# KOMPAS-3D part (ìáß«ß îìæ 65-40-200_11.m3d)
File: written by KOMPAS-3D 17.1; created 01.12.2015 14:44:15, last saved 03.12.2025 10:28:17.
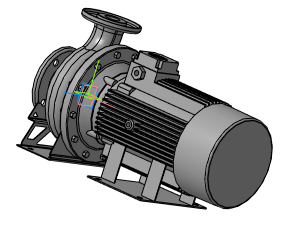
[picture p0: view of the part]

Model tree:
1. Операция без истории:3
